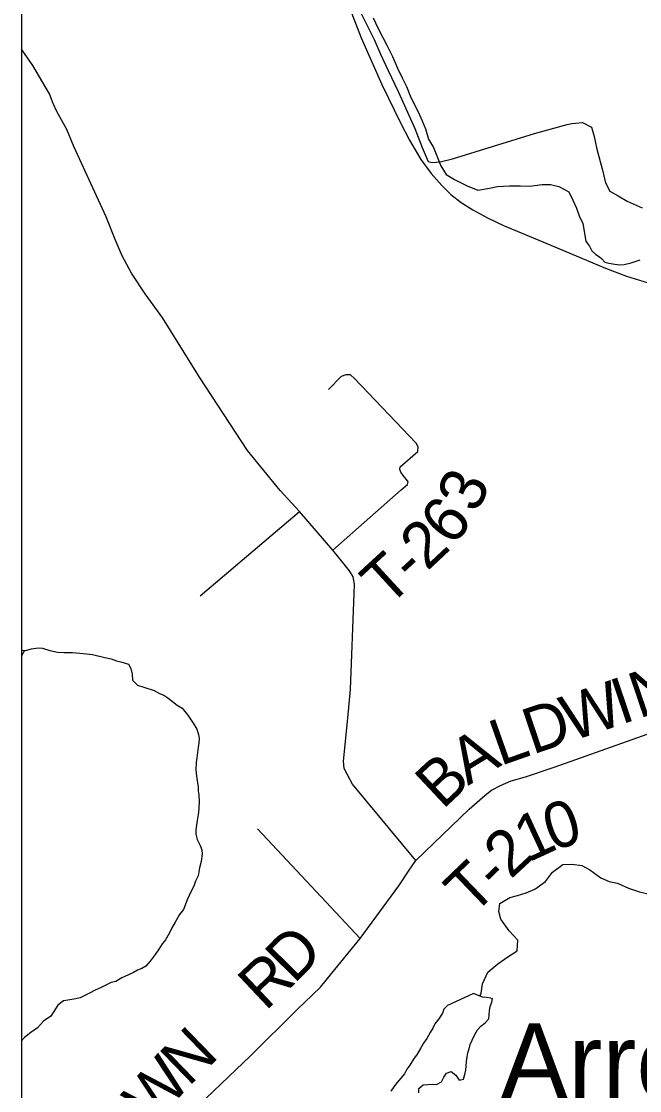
# Model space of a CAD drawing. Extents: x 0 to 34, y 0 to 22.
# Drawn here: x 2.1 to 2.866, y 19.406 to 20.729 of the extents above; entities that cross this region are included whole.
import ezdxf

# ---------------------------------------------------------------- set-up
doc = ezdxf.new("R2010")
doc.units = 0
for name, color, linetype in [('GM_X_Corporation', 7, 'Continuous'), ('GM_X_County_Road', 7, 'Continuous'), ('GM_X_County_Road_Text', 7, 'Continuous'), ('GM_X_Minor_Lake', 7, 'Continuous'), ('GM_X_Minor_Lake_Text', 7, 'Continuous'), ('GM_X_Minor_River', 7, 'Continuous'), ('GM_X_Rail_Line', 7, 'Continuous'), ('GM_X_Township_Road', 7, 'Continuous'), ('GM_X_Township_Road_Text', 7, 'Continuous'), ('SH_Data', 7, 'Continuous')]:
    doc.layers.add(name, color=color, linetype=linetype)

msp = doc.modelspace()

# ---------------------------------------------------------------- linework, layer by layer
at = {"layer": 'GM_X_Corporation'}
msp.add_lwpolyline([(2.1, 20.9), (2.1, 16.0934)], dxfattribs=at)
at = {"layer": 'GM_X_County_Road'}
for points in [[(2.5833, 19.6828), (2.5888, 19.6908), (2.5102, 19.7851), (2.504, 19.7967), (2.4999, 19.8046), (2.4989, 19.8135), (2.5044, 19.867), (2.5078, 19.9023), (2.5121, 20.0211), (2.5126, 20.0327), (2.5108, 20.0418), (2.5063, 20.0492), (2.4982, 20.0595), (2.4858, 20.0749), (2.4446, 20.1225), (2.4206, 20.1488), (2.3799, 20.1981), (2.3205, 20.2891), (2.2753, 20.362), (2.2532, 20.392), (2.2363, 20.4177), (2.2249, 20.4392), (2.216, 20.4592), (2.2049, 20.4873), (2.165, 20.5744), (2.1562, 20.5956), (2.1441, 20.6179), (2.1393, 20.6278), (2.135, 20.6394), (2.1141, 20.6745), (2.1, 20.6948)], [(2.1, 19.2238), (2.1306, 19.2398), (2.1687, 19.2646), (2.2183, 19.2987), (2.2483, 19.3203), (2.2708, 19.3364), (2.3018, 19.3705), (2.3839, 19.449), (2.4414, 19.5058), (2.4704, 19.5341), (2.4845, 19.5512), (2.5195, 19.5941), (2.5675, 19.6596), (2.5805, 19.6788), (2.5833, 19.6828)]]:
    msp.add_lwpolyline(points, dxfattribs=at)
at = {"layer": 'GM_X_Minor_Lake'}
msp.add_line((2.6284, 19.5117), (2.6598, 19.5261), dxfattribs=at)
for points in [[(2.5924, 19.4031), (2.5925, 19.4084), (2.5975, 19.4132), (2.6036, 19.4135), (2.6089, 19.4138), (2.6142, 19.4134), (2.6204, 19.4167), (2.6231, 19.4224), (2.6266, 19.4276), (2.6323, 19.4298), (2.638, 19.4252), (2.6424, 19.4187), (2.6478, 19.4201), (2.6494, 19.4258), (2.6506, 19.4314), (2.651, 19.4364), (2.6515, 19.4421), (2.6523, 19.4477), (2.6532, 19.4527), (2.6548, 19.4576), (2.656, 19.4629), (2.6583, 19.4685), (2.6618, 19.4753), (2.665, 19.481), (2.6692, 19.4858), (2.6746, 19.4899), (2.6792, 19.4948), (2.6793, 19.4997), (2.6797, 19.5047), (2.6806, 19.51), (2.6826, 19.5153), (2.6837, 19.52)], [(2.6815, 19.5202), (2.6835, 19.5199)], [(2.6836, 19.5199), (2.6837, 19.5199)], [(2.6284, 19.5117), (2.6235, 19.5066), (2.6216, 19.5017), (2.6169, 19.4946), (2.6122, 19.4886), (2.6095, 19.4833), (2.6064, 19.4777), (2.6021, 19.4705), (2.5982, 19.4645), (2.5947, 19.4588), (2.5901, 19.4509), (2.5858, 19.4449), (2.5811, 19.4374), (2.5773, 19.4325), (2.5745, 19.4269), (2.5699, 19.4212), (2.5649, 19.4156), (2.5614, 19.4107), (2.5575, 19.4051)]]:
    msp.add_lwpolyline(points, dxfattribs=at)
at = {"layer": 'GM_X_Minor_River'}
msp.add_line((2.104, 19.9508), (2.1, 19.9442), dxfattribs=at)
for points in [[(2.5357, 20.7336), (2.5416, 20.7213), (2.5477, 20.7091), (2.5532, 20.6991), (2.5598, 20.6857), (2.5659, 20.6712), (2.5717, 20.6593), (2.5772, 20.6486), (2.5826, 20.6352), (2.5917, 20.6172), (2.5964, 20.6061), (2.6007, 20.5961), (2.6043, 20.5835), (2.6105, 20.5732), (2.6155, 20.5606), (2.6195, 20.5506), (2.6261, 20.5399), (2.6366, 20.5336), (2.652, 20.5257), (2.6655, 20.5205), (2.68, 20.5229), (2.6899, 20.525), (2.7047, 20.5258), (2.7183, 20.5256), (2.7293, 20.5254), (2.7452, 20.5273), (2.7555, 20.5275), (2.7657, 20.525), (2.778, 20.5183), (2.7831, 20.508), (2.7875, 20.4981), (2.7911, 20.4885), (2.7954, 20.4789), (2.799, 20.4574)], [(2.799, 20.4574), (2.8012, 20.4543), (2.8038, 20.4509), (2.8067, 20.4451), (2.8116, 20.4408), (2.8161, 20.4377), (2.8191, 20.4354), (2.8229, 20.4311), (2.8278, 20.4299), (2.8327, 20.4291), (2.8403, 20.4278), (2.8468, 20.4284), (2.8555, 20.4306), (2.8663, 20.4342)], [(2.1, 19.951), (2.1053, 19.9507), (2.1126, 19.9529), (2.121, 19.9539), (2.1263, 19.9534), (2.1354, 19.9506), (2.1448, 19.9485), (2.1524, 19.948), (2.1581, 19.9483), (2.1635, 19.9482), (2.1726, 19.9473), (2.1805, 19.9464), (2.1881, 19.9455), (2.2033, 19.9418), (2.2112, 19.9405), (2.218, 19.9377), (2.2233, 19.9365), (2.2328, 19.9337), (2.2357, 19.9283), (2.2371, 19.9214), (2.2378, 19.9138), (2.2438, 19.9076), (2.2517, 19.9052), (2.2646, 19.9012), (2.271, 19.8976), (2.2766, 19.8952), (2.2815, 19.8921), (2.2931, 19.8828), (2.2992, 19.8793), (2.3062, 19.8708), (2.3129, 19.8608), (2.3173, 19.8531), (2.3195, 19.8466), (2.3202, 19.8416), (2.3197, 19.8359), (2.3189, 19.831), (2.3175, 19.8177), (2.3167, 19.812)], [(2.3167, 19.812), (2.3161, 19.8036), (2.3164, 19.7983), (2.3178, 19.7895), (2.3188, 19.7823), (2.3191, 19.777), (2.3198, 19.772), (2.3204, 19.7633), (2.3199, 19.7564), (2.3194, 19.75), (2.3177, 19.7401), (2.316, 19.7287), (2.3163, 19.7234), (2.3177, 19.7169), (2.3214, 19.7092), (2.3236, 19.7039), (2.3239, 19.6985), (2.3226, 19.6894), (2.3205, 19.6815), (2.3188, 19.6716), (2.3157, 19.6652), (2.3137, 19.6588), (2.3105, 19.6527), (2.3054, 19.6422), (2.3007, 19.6301), (2.296, 19.6241), (2.2905, 19.6143), (2.2858, 19.6064), (2.2834, 19.6011), (2.2787, 19.5924), (2.2745, 19.5876), (2.2702, 19.5812), (2.2659, 19.5744), (2.2597, 19.5661), (2.2542, 19.5598), (2.2492, 19.5572), (2.2439, 19.555), (2.2389, 19.5521), (2.2328, 19.5491), (2.2243, 19.5455), (2.217, 19.541), (2.2113, 19.5396), (2.1987, 19.5337), (2.1914, 19.5301), (2.1845, 19.5264), (2.1795, 19.5242), (2.173, 19.5209), (2.1676, 19.5194), (2.1577, 19.5181), (2.152, 19.5171), (2.1451, 19.5119), (2.1365, 19.4979), (2.1276, 19.492), (2.1199, 19.4838), (2.1118, 19.4778), (2.1037, 19.4715), (2.1, 19.4677)], [(2.6677, 19.5229), (2.6695, 19.5265), (2.6713, 19.5382), (2.6776, 19.5525), (2.69, 19.563), (2.7027, 19.5715), (2.7142, 19.5789), (2.7148, 19.5922), (2.7044, 19.6038), (2.694, 19.618), (2.6915, 19.6276), (2.6928, 19.6374), (2.7051, 19.6448), (2.7146, 19.6473), (2.7254, 19.6509), (2.7361, 19.6553), (2.7492, 19.6646), (2.7581, 19.6762), (2.7705, 19.6859), (2.7823, 19.6864), (2.7944, 19.6847), (2.8042, 19.6792), (2.8178, 19.6695), (2.8279, 19.6647), (2.8386, 19.6626), (2.8521, 19.6567), (2.8658, 19.6519), (2.8798, 19.6486)], [(2.6815, 19.5202), (2.6762, 19.5211), (2.6712, 19.5215), (2.6663, 19.5235), (2.661, 19.5258), (2.6598, 19.5261)]]:
    msp.add_lwpolyline(points, dxfattribs=at)
at = {"layer": 'GM_X_Rail_Line'}
msp.add_lwpolyline([(2.5089, 20.7397), (2.5211, 20.7088), (2.5465, 20.6512), (2.5698, 20.6036), (2.5807, 20.5824), (2.5948, 20.5582), (2.6074, 20.541), (2.6208, 20.526), (2.6321, 20.515), (2.6446, 20.5052), (2.6591, 20.4958), (2.6773, 20.486), (2.6974, 20.4768), (2.751, 20.4544), (2.8237, 20.4239), (2.8496, 20.4141), (2.8766, 20.4057)], dxfattribs=at)
at = {"layer": 'GM_X_Township_Road'}
for p, q in [((2.3214, 20.0182), (2.4446, 20.1225)), ((2.5195, 19.5941), (2.3923, 19.7301))]:
    msp.add_line(p, q, dxfattribs=at)
for points in [[(2.5195, 20.7415), (2.5369, 20.707), (2.5448, 20.6888), (2.5539, 20.6693), (2.5672, 20.6415), (2.5875, 20.5967), (2.5966, 20.5731), (2.604, 20.5557), (2.6089, 20.5545), (2.6187, 20.5554), (2.6339, 20.5592), (2.7357, 20.5906), (2.776, 20.6018), (2.7817, 20.6028), (2.7863, 20.6034), (2.7949, 20.6042), (2.8061, 20.5984), (2.8094, 20.5867), (2.8128, 20.571), (2.8194, 20.5469), (2.8235, 20.5295), (2.8288, 20.519), (2.8393, 20.5133), (2.8505, 20.5067), (2.8688, 20.4984)], [(2.5772, 20.1621), (2.5729, 20.1673), (2.5699, 20.1715), (2.5689, 20.1745), (2.5691, 20.178), (2.591, 20.1968), (2.5915, 20.2027), (2.5892, 20.2071), (2.5128, 20.2871), (2.5076, 20.2917), (2.5021, 20.292), (2.4963, 20.2896), (2.4804, 20.2736)], [(2.4858, 20.0749), (2.5704, 20.1496), (2.5784, 20.1561), (2.5793, 20.1592), (2.5772, 20.1621)], [(2.5888, 19.6908), (2.6545, 19.7541), (2.6743, 19.7718), (2.6824, 19.7777), (2.6936, 19.7835), (2.7066, 19.7892), (2.7245, 19.7944), (2.7612, 19.8068), (3.0474, 19.908), (3.064, 19.9124), (3.0742, 19.9129), (3.0864, 19.9117), (3.1054, 19.9069), (3.1155, 19.9034), (3.119, 19.9012)]]:
    msp.add_lwpolyline(points, dxfattribs=at)
at = {"layer": 'SH_Data'}
msp.add_line((2.1, 20.9), (2.1, 14.1), dxfattribs=at)

# ---------------------------------------------------------------- texts
at = {"layer": 'GM_X_County_Road_Text'}
for s, rotation, p in [('D', 45.4341, (2.4378, 19.5371)), ('R', 43.3549, (2.4023, 19.5035)), ('N', 44.1319, (2.307, 19.41)), ('W', 47.7704, (2.2635, 19.3619))]:
    msp.add_text(s, height=0.0568, rotation=rotation, dxfattribs=at).set_placement(p)
at = {"layer": 'GM_X_Minor_Lake_Text'}
msp.add_text('Arrowhead', height=0.0947, rotation=0.0004, dxfattribs=at).set_placement((2.6931, 19.3946))
at = {"layer": 'GM_X_Township_Road_Text'}
for s, rotation, p in [('3', 65.9915, (2.6644, 20.1192)), ('6', 50.8163, (2.6338, 20.0781)), ('2', 43.1672, (2.6026, 20.0482)), ('T', 42.5749, (2.5537, 20.0031)), ('-', 42.6802, (2.5851, 20.032)), ('N', 18.678, (2.8649, 19.8661)), ('I', 18.6764, (2.8428, 19.8587)), ('W', 18.6747, (2.7805, 19.8376)), ('D', 18.6895, (2.7331, 19.8216)), ('L', 19.465, (2.6932, 19.8075)), ('A', 31.0693, (2.6531, 19.783)), ('B', 43.2031, (2.6217, 19.7529)), ('0', 18.3049, (2.7579, 19.702)), ('1', 24.8169, (2.7277, 19.6879)), ('2', 42.8726, (2.706, 19.6668)), ('T', 43.8545, (2.6586, 19.6213)), ('-', 43.7745, (2.6893, 19.6508))]:
    msp.add_text(s, height=0.0568, rotation=rotation, dxfattribs=at).set_placement(p)

doc.saveas('drawing.dxf')
